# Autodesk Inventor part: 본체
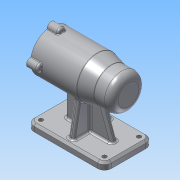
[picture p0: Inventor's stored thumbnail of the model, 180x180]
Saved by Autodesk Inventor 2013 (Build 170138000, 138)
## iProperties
Created: 2019-07
Part Number: 본체
Material: 알루미늄 6061
Document SubType Name: Modeling
Designer: Administrator
Density: 2.71 g/cm^3
Mass: 645.295 g
Surface Area: 654.416 cm^2
Volume: 238.116 cm^3
Author: Administrator
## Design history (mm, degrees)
sketch "스케치1"
  geometry: L1 (-46, 35)-(46, 35); L2 (56, 25)-(56, -25); L3 (46, -35)-(-46, -35); L4 (-56, -25)-(-56, 25); A1 r 10 centre (-46, 25) between (-46, 35) and (-56, 25); A2 r 10 centre (-46, -25) between (-56, -25) and (-46, -35); A3 r 10 centre (46, -25) between (46, -35) and (56, -25); A4 r 10 centre (46, 25) between (56, 25) and (46, 35); 7 further points
  constraints: 8 end point, 8 point on circle, 8 point on line, 8 tangent, 4 centre point, 3 equal radius, 2 midpoint, 2 parallel, 1 horizontal, 1 horizontal alignment, 1 perpendicular, 1 vertical alignment
  dimensions: "d0" = 112 distance of point (-56, 35) point (56, 35); "d2" = 70 distance of point (56, 35) point (56, -35); "d5" = 10 radius of A1
extrude "돌출1" new body sketch "스케치1" distance "d3" = 10; taper "d4" = 0 deg
sketch "스케치2"
  geometry: L1 (-56, 80)-(56, 80); L2 (-56, 105)-(-56, 80); L3 (-56, 105)-(-31, 105); L4 (-31, 105)-(-11, 110); L5 (-11, 110)-(56, 110); L6 (56, 110)-(56, 80); 3 further points
  constraints: 12 end point, 2 vertical alignment, 1 horizontal, 1 midpoint, 1 parallel, 1 perpendicular, 1 vertical
  dimensions: "d6" = 80 vertical distance of L1.end point (0, 0); "d7" = 60 diameter of L5 L1; "d8" = 50 diameter of L3 L1; "d9" = 45 distance from line of L4.end L2; "d10" = 25 distance of L3.end L2.start
revolve "회전1" sketch "스케치2" stored, may be unused: angle "d11" = 90 deg
sketch "스케치3"
  geometry: L1 (-56, 80)-(56, 80); L2 (-56, 55)-(-56, 105) reference; L3 (56, 50)-(56, 110) reference; L4 (-50, 80)-(-50, 90.5); L5 (-50, 90.5)-(-47, 90.5); L6 (-47, 90.5)-(-47, 96); L7 (-47, 96)-(-43, 96); L8 (-43, 96)-(-43, 97.5); L9 (-43, 97.5)-(-25, 97.5); L10 (-25, 97.5)-(-25, 101); L11 (-11, 50)-(-11, 110) reference; L12 (-25, 101)-(-13, 101); L13 (-13, 101)-(-13, 104); L14 (-13, 104)-(41, 104); L15 (41, 104)-(41, 101); L16 (41, 101)-(56, 101); 1 further point
  constraints: 26 end point, 8 parallel, 3 perpendicular, 2 midpoint, 2 point on line, 1 collinear, 1 horizontal
  dimensions: "d12" = 80 vertical distance of point (0, 0) L1.end; "d13" = 21 diameter of L5 L1; "d14" = 32 diameter of L7 L1; "d15" = 35 diameter of L9 L1; "d16" = 42 diameter of L16 L1; "d17" = 3 distance of L4.end L5.end; "d18" = 4 distance of L6.end L7.end; "d19" = 18 distance of L8.end L9.end; "d20" = 12 distance of L10.end L12.end; "d21" = 48 diameter of L14 L1; "d22" = 54 distance of L13.end L14.end; "d23" = 15 distance of L15.end L16.end; "d24" = 42 diameter of L12 L1
revolve "회전2" sketch "스케치3" stored, may be unused: angle "d25" = 90 deg
sketch "스케치4"
  geometry: L1 (-56, 25)-(-56, -25) reference; L2 (0, 4)-(-31, 4); L3 (-31, 4)-(-31, -4); L4 (-31, -4)-(0, -4); L5 (0, -4)-(0, 4); 2 further points
  constraints: 8 end point, 2 parallel, 1 coincident, 1 horizontal, 1 midpoint, 1 perpendicular
  dimensions: "d26" = 8 distance of L4.end L2.start; "d28" = 25 distance between parallel lines of L1 L3
extrude "돌출2" join sketch "스케치4" stored distance "d29" = 10; taper "d30" = 0 deg
sketch "스케치5"
  geometry: L1 (46, 10)-(-46, 10) reference; L2 (-36, 10)-(-20.57, 52.393); L3 (-56, 0)-(-56, 10) reference; L4 (-46, 10)-(-56, 10) reference; L5 (-31, 55)-(-11, 50) reference; 1 further point
  constraints: 2 end point, 2 point on line
  dimensions: "d31" = 20 distance from line of L2.start L3; "d32" = 110 deg angle of L2 L4
feature "리브1" sketch "스케치5" dims "d33" = 1, "d34" = 8, "d35" = 0, "d36" = 0, "d37" = 1, "d38" = 1
sketch "스케치6"
  geometry: L1 (-25, 10)-(-35, 10) reference; L2 (-28, 10)-(-19.654, 57.334); L3 (-35, 0)-(-35, 10) reference; 2 further points
  constraints: 2 end point, 1 point on line, 2 other
  dimensions: "d55" = 7 distance from line of L2.start L3; "d56" = 100 deg angle of L2 L1
feature "리브2" sketch "스케치6" dims "d40" = 1, "d41" = 8, "d42" = 0, "d43" = 0, "d44" = 1, "d45" = 1
sketch "스케치7"
  geometry: L1 (25, 10)-(-25, 10) reference; L2 (28, 10)-(19.654, 57.334); L3 (35, 10)-(25, 10) reference; L4 (35, 0)-(35, 10) reference; 2 further points
  constraints: 2 end point, 1 point on line, 2 other
  dimensions: "d46" = 100 deg angle of L2 L3; "d48" = 7 distance from line of L2.start L4
feature "리브3" sketch "스케치7" dims "d49" = 1, "d50" = 8, "d51" = 0, "d52" = 0, "d53" = 1, "d54" = 1
sketch "스케치8"
  geometry: C1 r 6 at (30, 0); 2 further points
  constraints: 2 horizontal alignment, 1 centre point, 1 other
  dimensions: "d57" = 12 diameter of C1
extrude "돌출3" join sketch "스케치8" distance "d60" = 16; taper "d61" = 0 deg
sketch "스케치9"
  geometry: A1 r 6 centre (0, 0) between (-0.6, -5.97) and (-0.6, 5.97) reference; 2 further points
  constraints: 1 coincident
hole "구멍1" sketch "스케치9" at (0, 0) diameter "d62" = 3.242; stored, may be unused: countersink angle "d66" = 90 deg, drill point angle "d68" = 118 deg; dims "d63" = 8, "d64" = 4, "d65" = 2, "d67" = 11
sketch "스케치10"
  geometry: C1 r 3 at (46, 25); C2 r 3 at (-46, 25); C3 r 3 at (-46, -25); C4 r 3 at (46, -25); A1 r 10 centre (46, 25) between (56, 25) and (46, 35) reference; A2 r 10 centre (46, -25) between (46, -35) and (56, -25) reference; A3 r 10 centre (-46, 25) between (-46, 35) and (-56, 25) reference; A4 r 10 centre (-46, -25) between (-56, -25) and (-46, -35) reference; 1 further point
  constraints: 4 centre point, 4 coincident, 3 equal radius
  dimensions: "d72" = 6 diameter of C1
extrude "돌출4" cut sketch "스케치10" distance "d74" = 16; taper "d75" = 0 deg
node "작업 평면1"
sketch "스케치11"
  geometry: L1 (33.5, -29.4)-(33.5, -5.97) reference; L2 (23.5, -80)-(-68.5, -80) reference; 2 further points
  constraints: 1 other
  dimensions: "d76" = 42 distance from line of L1 point (-8.5, 0); "d77" = 80 distance from line of L2 point (-8.5, 0)
feature "엠보싱1" sketch "스케치11" dims "d0" = 112, "d2" = 70, "d5" = 10, "d78" = 0.5, "d79" = 0
fillet "모깎기1" dims "d80" = 0.3
fillet "모깎기2" dims "d81" = 10
fillet "모깎기4" dims "d83" = 3
fillet "모깎기5" dims "d84" = 3
fillet "모깎기6" dims "d85" = 3
chamfer "모따기1" distance "d86" = 3; stored, may be unused: second distance "d87" = 2, angle "d88" = 45 deg
chamfer "모따기2" distance "d89" = 1; stored, may be unused: second distance "d90" = 2, angle "d91" = 45 deg
fillet "모깎기7" dims "d92" = 3
fillet "모깎기8" dims "d93" = 1
fillet "모깎기9" dims "d94" = 3
fillet "모깎기10" dims "d95" = 3
fillet "모깎기11" dims "d96" = 3
node "솔리드1"
pattern_circular "원형 패턴1" dims angle "d70" = 360 deg
